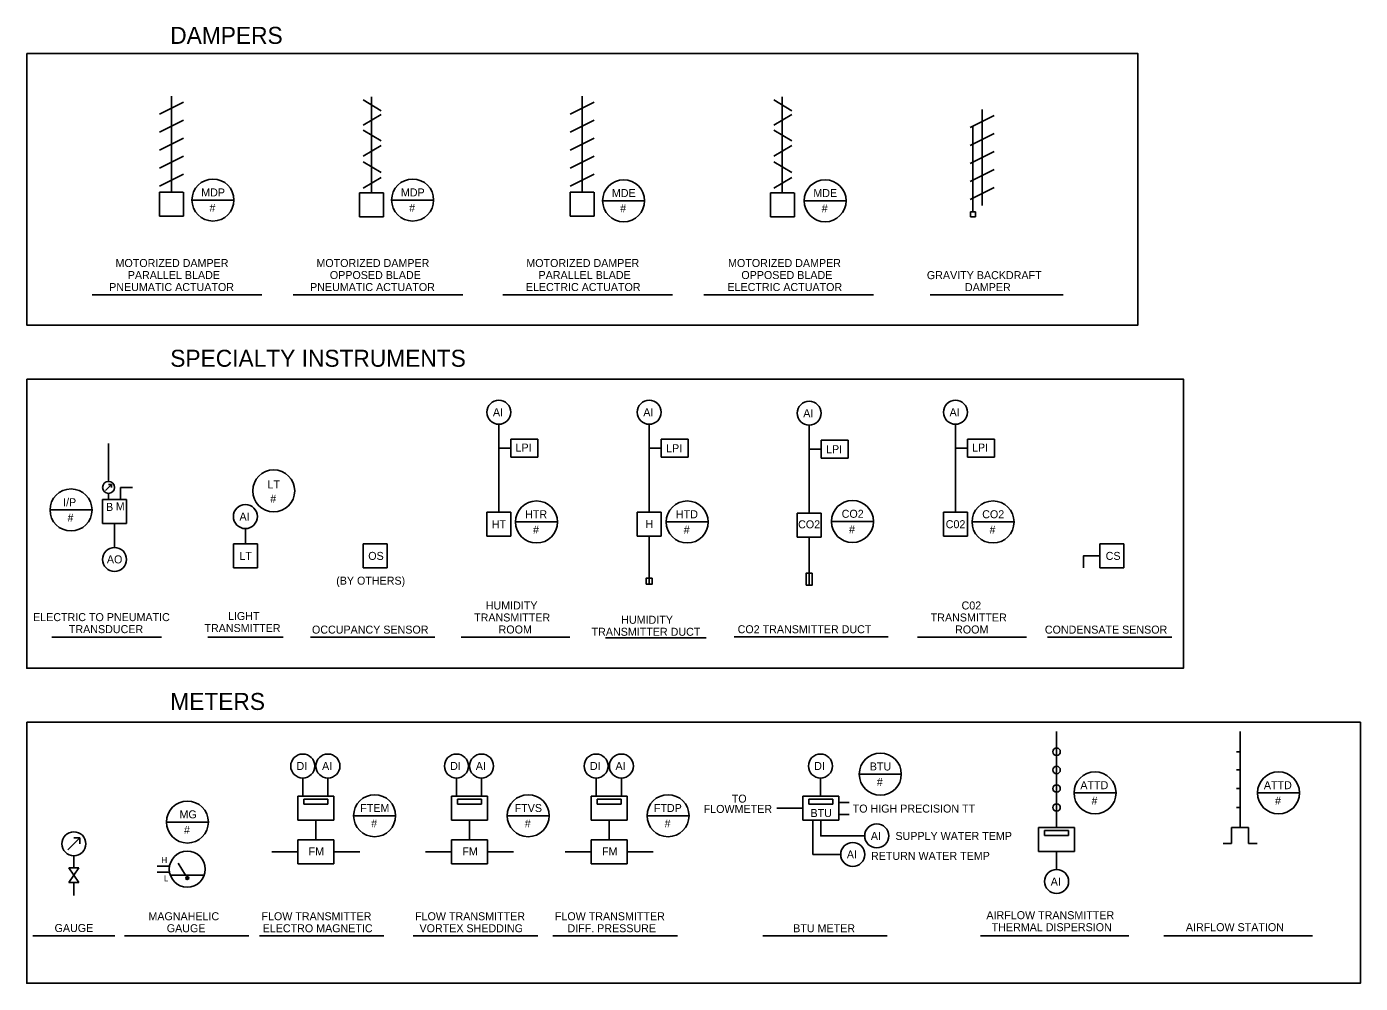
# Model space of a CAD drawing. Extents: x 10015 to 10283, y 10002 to 10184.
# Drawn here: x 10015.5 to 10126.6, y 10007.9 to 10087.6 of the extents above; entities that cross this region are included whole.
import ezdxf

# ---------------------------------------------------------------- set-up
doc = ezdxf.new("R2010")
doc.units = 0
for name, color, linetype in [('G-ANNO-TEXT', 7, 'Continuous'), ('G-DETL-LINE', 7, 'Continuous'), ('G-DETL-TEXT', 7, 'Continuous'), ('M-ANNO-NPLT', 7, 'Continuous')]:
    doc.layers.add(name, color=color, linetype=linetype)

msp = doc.modelspace()

# ---------------------------------------------------------------- linework, layer by layer
at = {"layer": 'G-ANNO-TEXT'}
for p, q in [((10020.95, 10065.25), (10035.09, 10065.25)), ((10037.69, 10065.25), (10051.83, 10065.25)), ((10055.18, 10065.25), (10069.32, 10065.25)), ((10071.93, 10065.25), (10086.07, 10065.25)), ((10090.77, 10065.25), (10101.86, 10065.25)), ((10017.59, 10036.72), (10026.74, 10036.72)), ((10030.58, 10036.72), (10036.87, 10036.72)), ((10039.15, 10036.72), (10049.52, 10036.72)), ((10051.69, 10036.72), (10060.76, 10036.72)), ((10063.73, 10036.67), (10072.11, 10036.67)), ((10074.45, 10036.74), (10087.28, 10036.74)), ((10089.73, 10036.72), (10098.81, 10036.72)), ((10100.55, 10036.72), (10110.92, 10036.72)), ((10016.01, 10011.84), (10022.84, 10011.84)), ((10023.64, 10011.84), (10034.01, 10011.84)), ((10034.9, 10011.84), (10045.27, 10011.84)), ((10047.71, 10011.84), (10058.08, 10011.84)), ((10059.35, 10011.84), (10069.72, 10011.84)), ((10076.83, 10011.84), (10087.2, 10011.84)), ((10094.97, 10011.84), (10107.35, 10011.84)), ((10110.26, 10011.84), (10122.64, 10011.84))]:
    msp.add_line(p, q, dxfattribs=at)
at = {"layer": 'G-DETL-LINE'}
for p, q in [((10026.56, 10080.29), (10028.56, 10081.29)), ((10027.56, 10081.79), (10027.56, 10073.79)), ((10045.04, 10080.58), (10043.53, 10081.48)), ((10044.23, 10081.73), (10044.23, 10073.73)), ((10060.79, 10080.29), (10062.79, 10081.29)), ((10061.79, 10081.79), (10061.79, 10073.79)), ((10079.27, 10080.58), (10077.76, 10081.48)), ((10078.46, 10081.73), (10078.46, 10073.73)), ((10045.04, 10080.26), (10043.53, 10079.37)), ((10079.27, 10080.26), (10077.76, 10079.37)), ((10094.11, 10079.19), (10096.11, 10080.19)), ((10095.11, 10080.69), (10095.11, 10072.69)), ((10026.56, 10078.79), (10028.56, 10079.79)), ((10045.04, 10078.08), (10043.53, 10078.97)), ((10060.79, 10078.79), (10062.79, 10079.79)), ((10079.27, 10078.08), (10077.76, 10078.97)), ((10094.11, 10077.69), (10096.11, 10078.69)), ((10094.35, 10079.33), (10094.35, 10072.16)), ((10026.56, 10077.29), (10028.56, 10078.29)), ((10045.04, 10077.68), (10043.53, 10076.79)), ((10060.79, 10077.29), (10062.79, 10078.29)), ((10079.27, 10077.68), (10077.76, 10076.79)), ((10026.56, 10075.79), (10028.56, 10076.79)), ((10060.79, 10075.79), (10062.79, 10076.79)), ((10094.11, 10076.19), (10096.11, 10077.19)), ((10045.04, 10075.43), (10043.53, 10076.32)), ((10079.27, 10075.43), (10077.76, 10076.32)), ((10094.11, 10074.69), (10096.11, 10075.69)), ((10026.56, 10074.29), (10028.56, 10075.29)), ((10045.04, 10075.03), (10043.53, 10074.14)), ((10060.79, 10074.29), (10062.79, 10075.29)), ((10079.27, 10075.03), (10077.76, 10074.14)), ((10026.56, 10073.79), (10028.54, 10073.79)), ((10026.56, 10073.79), (10026.56, 10071.79)), ((10028.56, 10071.79), (10028.56, 10073.79)), ((10043.24, 10073.73), (10045.22, 10073.73)), ((10043.24, 10073.73), (10043.24, 10071.73)), ((10045.24, 10071.73), (10045.24, 10073.73)), ((10060.79, 10073.79), (10062.77, 10073.79)), ((10060.79, 10073.79), (10060.79, 10071.79)), ((10062.79, 10071.79), (10062.79, 10073.79)), ((10077.47, 10073.73), (10079.45, 10073.73)), ((10077.47, 10073.73), (10077.47, 10071.73)), ((10079.47, 10071.73), (10079.47, 10073.73)), ((10094.11, 10073.19), (10096.11, 10074.19)), ((10094.14, 10072.16), (10094.56, 10072.16)), ((10094.14, 10072.16), (10094.14, 10071.74)), ((10094.56, 10072.16), (10094.56, 10071.74)), ((10026.56, 10071.79), (10028.56, 10071.79)), ((10043.24, 10071.73), (10045.24, 10071.73)), ((10060.79, 10071.79), (10062.79, 10071.79)), ((10077.47, 10071.73), (10079.47, 10071.73)), ((10094.14, 10071.74), (10094.56, 10071.74)), ((10054.84, 10047.14), (10054.84, 10054.46)), ((10067.37, 10047.14), (10067.37, 10054.46)), ((10080.7, 10047.05), (10080.7, 10054.38)), ((10092.89, 10047.14), (10092.89, 10054.46)), ((10058.09, 10053.21), (10055.84, 10053.21)), ((10055.84, 10053.21), (10055.84, 10051.71)), ((10058.09, 10051.71), (10058.09, 10053.21)), ((10070.62, 10053.21), (10068.37, 10053.21)), ((10068.37, 10053.21), (10068.37, 10051.71)), ((10070.62, 10051.71), (10070.62, 10053.21)), ((10083.95, 10053.13), (10081.7, 10053.13)), ((10081.7, 10053.13), (10081.7, 10051.63)), ((10083.95, 10051.63), (10083.95, 10053.13)), ((10096.14, 10053.21), (10093.89, 10053.21)), ((10093.89, 10053.21), (10093.89, 10051.71)), ((10096.14, 10051.71), (10096.14, 10053.21)), ((10022.32, 10052.86), (10022.32, 10049.7)), ((10055.84, 10052.46), (10054.84, 10052.46)), ((10068.37, 10052.46), (10067.37, 10052.46)), ((10081.7, 10052.38), (10080.7, 10052.38)), ((10093.89, 10052.46), (10092.89, 10052.46)), ((10055.84, 10051.71), (10058.09, 10051.71)), ((10068.37, 10051.71), (10070.62, 10051.71)), ((10081.7, 10051.63), (10083.95, 10051.63)), ((10093.89, 10051.71), (10096.14, 10051.71)), ((10022.07, 10048.95), (10022.57, 10049.45)), ((10022.57, 10049.45), (10022.32, 10049.45)), ((10022.32, 10048.2), (10022.32, 10048.7)), ((10022.57, 10049.2), (10022.57, 10049.45)), ((10023.32, 10048.2), (10023.32, 10049.2)), ((10023.32, 10049.2), (10024.32, 10049.2)), ((10023.82, 10048.2), (10021.82, 10048.2)), ((10021.82, 10048.2), (10021.82, 10046.2)), ((10023.82, 10046.2), (10023.82, 10048.2)), ((10053.84, 10047.14), (10053.84, 10045.14)), ((10055.84, 10047.14), (10053.84, 10047.14)), ((10055.84, 10045.14), (10055.84, 10047.14)), ((10066.37, 10047.14), (10066.37, 10045.14)), ((10068.37, 10047.14), (10066.37, 10047.14)), ((10068.37, 10045.14), (10068.37, 10047.14)), ((10079.7, 10047.05), (10079.7, 10045.05)), ((10081.7, 10047.05), (10079.7, 10047.05)), ((10081.7, 10045.05), (10081.7, 10047.05)), ((10091.89, 10047.14), (10091.89, 10045.14)), ((10093.89, 10047.14), (10091.89, 10047.14)), ((10093.89, 10045.14), (10093.89, 10047.14)), ((10021.82, 10046.2), (10023.82, 10046.2)), ((10022.82, 10046.2), (10022.82, 10044.2)), ((10033.72, 10044.49), (10033.72, 10045.77)), ((10032.72, 10044.49), (10032.72, 10042.49)), ((10034.72, 10044.49), (10032.72, 10044.49)), ((10034.72, 10042.49), (10034.72, 10044.49)), ((10043.53, 10044.49), (10043.53, 10042.49)), ((10045.53, 10044.49), (10043.53, 10044.49)), ((10045.53, 10042.49), (10045.53, 10044.49)), ((10053.84, 10045.14), (10055.84, 10045.14)), ((10068.37, 10045.14), (10066.37, 10045.14)), ((10068.37, 10045.14), (10066.37, 10045.14)), ((10067.37, 10041.14), (10067.37, 10045.14)), ((10079.7, 10045.05), (10081.7, 10045.05)), ((10080.7, 10045.05), (10080.7, 10041.05)), ((10091.89, 10045.14), (10093.89, 10045.14)), ((10104.93, 10044.49), (10104.93, 10042.49)), ((10106.93, 10044.49), (10104.93, 10044.49)), ((10106.93, 10042.49), (10106.93, 10044.49)), ((10032.72, 10042.49), (10034.72, 10042.49)), ((10043.53, 10042.49), (10045.53, 10042.49)), ((10104.93, 10042.49), (10106.93, 10042.49)), ((10101.32, 10028.86), (10101.32, 10020.86)), ((10116.61, 10028.86), (10116.61, 10020.86)), ((10116.61, 10027.18), (10116.3, 10027.18)), ((10116.61, 10025.66), (10116.3, 10025.66)), ((10038.5, 10024.99), (10038.5, 10023.5)), ((10040.6, 10024.99), (10040.6, 10023.5)), ((10051.31, 10024.99), (10051.31, 10023.5)), ((10053.4, 10024.99), (10053.4, 10023.5)), ((10062.95, 10024.99), (10062.95, 10023.5)), ((10065.05, 10024.99), (10065.05, 10023.5)), ((10081.64, 10024.99), (10081.64, 10023.5)), ((10038.09, 10021.48), (10038.09, 10023.48)), ((10038.09, 10023.48), (10041.09, 10023.48)), ((10038.59, 10022.82), (10038.59, 10023.23)), ((10038.59, 10023.23), (10040.59, 10023.23)), ((10040.59, 10022.82), (10040.59, 10023.23)), ((10041.09, 10021.48), (10041.09, 10023.48)), ((10050.9, 10021.48), (10050.9, 10023.48)), ((10050.9, 10023.48), (10053.9, 10023.48)), ((10051.4, 10022.82), (10051.4, 10023.23)), ((10051.4, 10023.23), (10053.4, 10023.23)), ((10053.4, 10022.82), (10053.4, 10023.23)), ((10053.9, 10021.48), (10053.9, 10023.48)), ((10062.54, 10021.48), (10062.54, 10023.48)), ((10062.54, 10023.48), (10065.54, 10023.48)), ((10063.04, 10022.82), (10063.04, 10023.23)), ((10063.04, 10023.23), (10065.04, 10023.23)), ((10065.04, 10022.82), (10065.04, 10023.23)), ((10065.54, 10021.48), (10065.54, 10023.48)), ((10080.17, 10021.48), (10080.17, 10023.48)), ((10080.17, 10023.48), (10083.17, 10023.48)), ((10080.67, 10022.82), (10080.67, 10023.23)), ((10080.67, 10023.23), (10082.67, 10023.23)), ((10082.67, 10022.82), (10082.67, 10023.23)), ((10083.17, 10021.48), (10083.17, 10023.48)), ((10116.61, 10024.11), (10116.3, 10024.11)), ((10038.59, 10022.82), (10040.59, 10022.82)), ((10051.4, 10022.82), (10053.4, 10022.82)), ((10063.04, 10022.82), (10065.04, 10022.82)), ((10080.17, 10022.48), (10078.01, 10022.48)), ((10080.67, 10022.82), (10082.67, 10022.82)), ((10084.03, 10022.94), (10083.18, 10022.94)), ((10116.61, 10022.54), (10116.3, 10022.54)), ((10038.09, 10021.48), (10041.09, 10021.48)), ((10039.59, 10021.48), (10039.59, 10019.84)), ((10050.9, 10021.48), (10053.9, 10021.48)), ((10052.4, 10021.48), (10052.4, 10019.84)), ((10062.54, 10021.48), (10065.54, 10021.48)), ((10064.04, 10021.48), (10064.04, 10019.84)), ((10080.17, 10021.48), (10083.17, 10021.48)), ((10084.03, 10021.94), (10083.17, 10021.94)), ((10018.93, 10019.01), (10019.93, 10020.01)), ((10019.93, 10020.01), (10019.43, 10020.01)), ((10019.93, 10019.51), (10019.93, 10020.01)), ((10038.09, 10017.84), (10038.09, 10019.84)), ((10038.09, 10019.84), (10041.09, 10019.84)), ((10041.09, 10017.84), (10041.09, 10019.84)), ((10050.9, 10017.84), (10050.9, 10019.84)), ((10050.9, 10019.84), (10053.9, 10019.84)), ((10053.9, 10017.84), (10053.9, 10019.84)), ((10062.54, 10017.84), (10062.54, 10019.84)), ((10062.54, 10019.84), (10065.54, 10019.84)), ((10065.54, 10017.84), (10065.54, 10019.84)), ((10099.82, 10018.86), (10099.82, 10020.86)), ((10099.82, 10020.86), (10102.82, 10020.86)), ((10100.32, 10020.2), (10100.32, 10020.61)), ((10100.32, 10020.61), (10102.32, 10020.61)), ((10100.32, 10020.2), (10102.32, 10020.2)), ((10102.32, 10020.2), (10102.32, 10020.61)), ((10102.82, 10018.86), (10102.82, 10020.86)), ((10115.9, 10020.86), (10115.9, 10019.54)), ((10115.9, 10020.86), (10117.32, 10020.86)), ((10117.32, 10019.54), (10117.32, 10020.86)), ((10038.09, 10018.84), (10035.93, 10018.84)), ((10043.25, 10018.84), (10041.09, 10018.84)), ((10050.9, 10018.84), (10048.74, 10018.84)), ((10056.06, 10018.84), (10053.9, 10018.84)), ((10062.54, 10018.84), (10060.38, 10018.84)), ((10067.7, 10018.84), (10065.54, 10018.84)), ((10099.82, 10018.86), (10102.82, 10018.86)), ((10101.32, 10018.86), (10101.32, 10017.37)), ((10115.9, 10019.54), (10115.19, 10019.54)), ((10118.03, 10019.54), (10117.32, 10019.54)), ((10019.43, 10017.51), (10019.43, 10018.51)), ((10026.36, 10017.66), (10027.4, 10017.66)), ((10028.73, 10016.9), (10028.13, 10017.9)), ((10038.09, 10017.84), (10041.09, 10017.84)), ((10050.9, 10017.84), (10053.9, 10017.84)), ((10062.54, 10017.84), (10065.54, 10017.84)), ((10019.02, 10016.28), (10019.84, 10017.51)), ((10019.84, 10016.28), (10019.02, 10017.51)), ((10019.02, 10017.51), (10019.84, 10017.51)), ((10026.36, 10017.16), (10027.38, 10017.16)), ((10027.46, 10016.9), (10030.29, 10016.9)), ((10028.88, 10016.65), (10028.75, 10016.65)), ((10029, 10016.65), (10028.88, 10016.65)), ((10019.84, 10016.28), (10019.02, 10016.28)), ((10019.43, 10016.28), (10019.43, 10015.19))]:
    msp.add_line(p, q, dxfattribs=at)
for points in [[(10015.5, 10085.34), (10108.09, 10085.34), (10108.09, 10062.72), (10015.5, 10062.72)], [(10015.5, 10058.22), (10111.89, 10058.22), (10111.89, 10034.13), (10015.5, 10034.13)], [(10080.45, 10041.05), (10080.45, 10042.05), (10080.95, 10042.05), (10080.95, 10041.05)], [(10067.62, 10041.64), (10067.62, 10041.14), (10067.12, 10041.14), (10067.12, 10041.64)], [(10015.5, 10029.64), (10126.63, 10029.64), (10126.63, 10007.89), (10015.5, 10007.89)]]:
    msp.add_lwpolyline(points, close=True, dxfattribs=at)
for points in [[(10104.93, 10043.49), (10103.56, 10043.49), (10103.56, 10042.49)], [(10081.01, 10021.48), (10081.01, 10018.62), (10083.33, 10018.62)], [(10081.67, 10021.48), (10081.67, 10020.17), (10085.33, 10020.17)]]:
    msp.add_lwpolyline(points, dxfattribs=at)
for centre, radius in [((10054.84, 10055.46), 1), ((10067.37, 10055.46), 1), ((10092.89, 10055.46), 1), ((10080.7, 10055.38), 1), ((10022.32, 10049.2), 0.5), ((10033.72, 10046.77), 1), ((10022.82, 10043.2), 1), ((10038.5, 10025.99), 1), ((10040.6, 10025.99), 1), ((10051.31, 10025.99), 1), ((10053.4, 10025.99), 1), ((10062.95, 10025.99), 1), ((10065.05, 10025.99), 1), ((10081.64, 10025.99), 1), ((10101.32, 10027.18), 0.308), ((10101.32, 10025.66), 0.308), ((10101.32, 10024.11), 0.308), ((10101.32, 10022.53), 0.308), ((10086.33, 10020.17), 1), ((10019.43, 10019.51), 1), ((10028.88, 10017.4), 1.5), ((10084.33, 10018.62), 1), ((10101.32, 10016.37), 1)]:
    msp.add_circle(centre, radius, dxfattribs=at)
for start, end in [(0, 180), (180, 0)]:
    msp.add_arc((10028.88, 10016.65), 0.125, start, end, dxfattribs=at)
at = {"layer": 'G-DETL-TEXT'}
msp.add_line((10017.44, 10047.32), (10020.94, 10047.32), dxfattribs=at)
for centre in [(10031.02, 10073.14), (10047.66, 10073.14), (10065.24, 10073.08), (10082.03, 10073.08), (10036.08, 10048.91), (10019.19, 10047.32), (10057.98, 10046.32), (10070.54, 10046.32), (10084.31, 10046.36), (10096.02, 10046.32), (10086.63, 10025.31), (10104.52, 10023.75), (10119.81, 10023.75), (10044.49, 10021.85), (10057.29, 10021.85), (10068.94, 10021.85), (10028.89, 10021.32)]:
    msp.add_circle(centre, 1.75, dxfattribs=at)
at = {"layer": 'M-ANNO-NPLT'}
for p, q in [((10029.27, 10073.14), (10032.77, 10073.14)), ((10045.91, 10073.14), (10049.41, 10073.14)), ((10063.49, 10073.08), (10066.99, 10073.08)), ((10080.28, 10073.08), (10083.78, 10073.08)), ((10056.23, 10046.32), (10059.73, 10046.32)), ((10068.79, 10046.32), (10072.29, 10046.32)), ((10082.56, 10046.36), (10086.06, 10046.36)), ((10094.27, 10046.32), (10097.77, 10046.32)), ((10084.88, 10025.31), (10088.38, 10025.31)), ((10102.77, 10023.75), (10106.27, 10023.75)), ((10118.06, 10023.75), (10121.56, 10023.75)), ((10027.14, 10021.32), (10030.64, 10021.32)), ((10042.74, 10021.85), (10046.24, 10021.85)), ((10055.54, 10021.85), (10059.04, 10021.85)), ((10067.19, 10021.85), (10070.69, 10021.85))]:
    msp.add_line(p, q, dxfattribs=at)

# ---------------------------------------------------------------- texts
at = {"layer": 'G-ANNO-TEXT'}
for s, height, p in [('DAMPERS', 1.417, (10027.46, 10086.15)), ('MOTORIZED DAMPER', 0.6667, (10022.9, 10067.56)), ('MOTORIZED DAMPER', 0.6667, (10039.64, 10067.56)), ('MOTORIZED DAMPER', 0.6667, (10057.13, 10067.56)), ('MOTORIZED DAMPER', 0.6667, (10073.94, 10067.56)), ('PARALLEL BLADE', 0.6667, (10023.92, 10066.56)), ('OPPOSED BLADE', 0.6667, (10040.76, 10066.56)), ('PARALLEL BLADE', 0.6667, (10058.15, 10066.56)), ('OPPOSED BLADE', 0.6667, (10075.05, 10066.56)), ('GRAVITY BACKDRAFT', 0.6667, (10090.51, 10066.55)), ('PNEUMATIC ACTUATOR', 0.6667, (10022.37, 10065.56)), ('PNEUMATIC ACTUATOR', 0.6667, (10039.11, 10065.56)), ('ELECTRIC ACTUATOR', 0.6667, (10057.09, 10065.56)), ('ELECTRIC ACTUATOR', 0.6667, (10073.89, 10065.56)), ('DAMPER', 0.667, (10093.68, 10065.55)), ('SPECIALTY INSTRUMENTS', 1.4167, (10027.46, 10059.25)), ('ELECTRIC TO PNEUMATIC', 0.6667, (10016.03, 10038.06)), ('LIGHT', 0.667, (10032.27, 10038.15)), ('TRANSMITTER', 0.6667, (10052.78, 10038.03)), ('HUMIDITY', 0.667, (10053.75, 10039.03)), ('TRANSMITTER', 0.6667, (10090.83, 10038.03)), ('C02', 0.667, (10093.4, 10039.03)), ('TRANSDUCER', 0.667, (10019.01, 10037.06)), ('TRANSMITTER', 0.6667, (10030.31, 10037.15)), ('OCCUPANCY SENSOR', 0.6667, (10039.27, 10037.02)), ('ROOM', 0.667, (10054.82, 10037.03)), ('HUMIDITY', 0.667, (10065.04, 10037.84)), ('CO2 TRANSMITTER DUCT ', 0.6667, (10074.74, 10037.05)), ('ROOM', 0.667, (10092.86, 10037.03)), ('CONDENSATE SENSOR', 0.6667, (10100.34, 10037.02)), ('TRANSMITTER DUCT', 0.6667, (10062.57, 10036.84)), ('METERS', 1.417, (10027.46, 10030.66)), ('MAGNAHELIC ', 0.6667, (10025.64, 10013.14)), ('FLOW TRANSMITTER', 0.6667, (10035.06, 10013.14)), ('FLOW TRANSMITTER', 0.6667, (10047.86, 10013.14)), ('FLOW TRANSMITTER', 0.6667, (10059.51, 10013.14)), ('AIRFLOW TRANSMITTER', 0.6667, (10095.47, 10013.23)), ('GAUGE', 0.667, (10017.82, 10012.16)), ('GAUGE', 0.667, (10027.17, 10012.14)), ('ELECTRO MAGNETIC', 0.6667, (10035.16, 10012.14)), ('VORTEX SHEDDING', 0.6667, (10048.23, 10012.14)), ('DIFF. PRESSURE', 0.6667, (10060.56, 10012.14)), ('BTU METER', 0.667, (10079.37, 10012.14)), ('THERMAL DISPERSION', 0.6667, (10095.91, 10012.23)), ('AIRFLOW STATION', 0.6667, (10112.09, 10012.23))]:
    msp.add_text(s, height=height, dxfattribs=at).set_placement(p)
at = {"layer": 'G-DETL-LINE'}
for s, height, p in [('AI', 0.667, (10054.35, 10055.13)), ('AI', 0.667, (10066.88, 10055.13)), ('AI', 0.667, (10080.21, 10055.05)), ('AI', 0.667, (10092.4, 10055.13)), ('LPI', 0.667, (10056.23, 10052.19)), ('LPI', 0.667, (10068.78, 10052.13)), ('LPI', 0.667, (10082.11, 10052.05)), ('LPI', 0.667, (10094.27, 10052.19)), ('B', 0.667, (10022.11, 10047.24)), ('M', 0.667, (10022.92, 10047.3)), ('AI', 0.667, (10033.23, 10046.44)), ('HT', 0.667, (10054.25, 10045.8)), ('H', 0.667, (10067.06, 10045.81)), ('CO2', 0.667, (10079.78, 10045.79)), ('C02', 0.667, (10092.08, 10045.8)), ('AO', 0.667, (10022.18, 10042.87)), ('LT', 0.667, (10033.22, 10043.16)), ('OS', 0.667, (10043.96, 10043.16)), ('CS', 0.667, (10105.41, 10043.16)), ('(BY OTHERS)', 0.6667, (10041.29, 10041.1)), ('DI', 0.667, (10037.98, 10025.66)), ('AI', 0.667, (10040.11, 10025.66)), ('DI', 0.667, (10050.78, 10025.66)), ('AI', 0.667, (10052.92, 10025.66)), ('DI', 0.667, (10062.43, 10025.66)), ('AI', 0.667, (10064.56, 10025.66)), ('DI', 0.667, (10081.12, 10025.66)), ('TO ', 0.667, (10074.25, 10022.94)), ('FLOWMETER', 0.667, (10071.91, 10022.08)), ('BTU', 0.667, (10080.81, 10021.74)), (' TO HIGH PRECISION TT', 0.6667, (10084.08, 10022.11)), ('AI', 0.667, (10085.84, 10019.83)), ('SUPPLY WATER TEMP', 0.6667, (10087.89, 10019.83)), ('FM', 0.667, (10038.99, 10018.54)), ('FM', 0.667, (10051.8, 10018.54)), ('FM', 0.667, (10063.44, 10018.54)), ('AI', 0.667, (10083.84, 10018.29)), ('RETURN WATER TEMP', 0.6667, (10085.85, 10018.17)), ('H', 0.5, (10026.72, 10017.91)), ('L', 0.5, (10026.93, 10016.38)), ('AI', 0.667, (10100.83, 10016.03))]:
    msp.add_text(s, height=height, dxfattribs=at).set_placement(p)
at = {"layer": 'G-DETL-TEXT'}
for s, p in [('MDP', (10030.04, 10073.44)), ('MDP', (10046.68, 10073.44)), ('MDE', (10064.26, 10073.39)), ('MDE', (10081.05, 10073.39)), ('#', (10030.73, 10072.16)), ('#', (10047.37, 10072.16)), ('#', (10064.95, 10072.11)), ('#', (10081.74, 10072.11)), ('LT', (10035.56, 10049.11)), ('I/P', (10018.53, 10047.63)), ('#', (10035.79, 10047.93)), ('#', (10018.9, 10046.34)), ('HTR', (10057.03, 10046.63)), ('HTD', (10069.6, 10046.63)), ('CO2', (10083.41, 10046.67)), ('CO2', (10095.12, 10046.63)), ('#', (10057.69, 10045.35)), ('#', (10070.25, 10045.35)), ('#', (10084.02, 10045.38)), ('#', (10095.73, 10045.35)), ('BTU', (10085.75, 10025.62)), ('#', (10086.34, 10024.33)), ('ATTD', (10103.3, 10024.06)), ('ATTD', (10118.59, 10024.06)), ('#', (10104.23, 10022.77)), ('#', (10119.52, 10022.77)), ('MG', (10028.23, 10021.63)), ('FTEM', (10043.29, 10022.16)), ('FTVS', (10056.16, 10022.16)), ('FTDP', (10067.76, 10022.16)), ('#', (10028.6, 10020.34)), ('#', (10044.2, 10020.87)), ('#', (10057, 10020.87)), ('#', (10068.65, 10020.87))]:
    msp.add_text(s, height=0.667, dxfattribs=at).set_placement(p)

doc.saveas('drawing.dxf')
